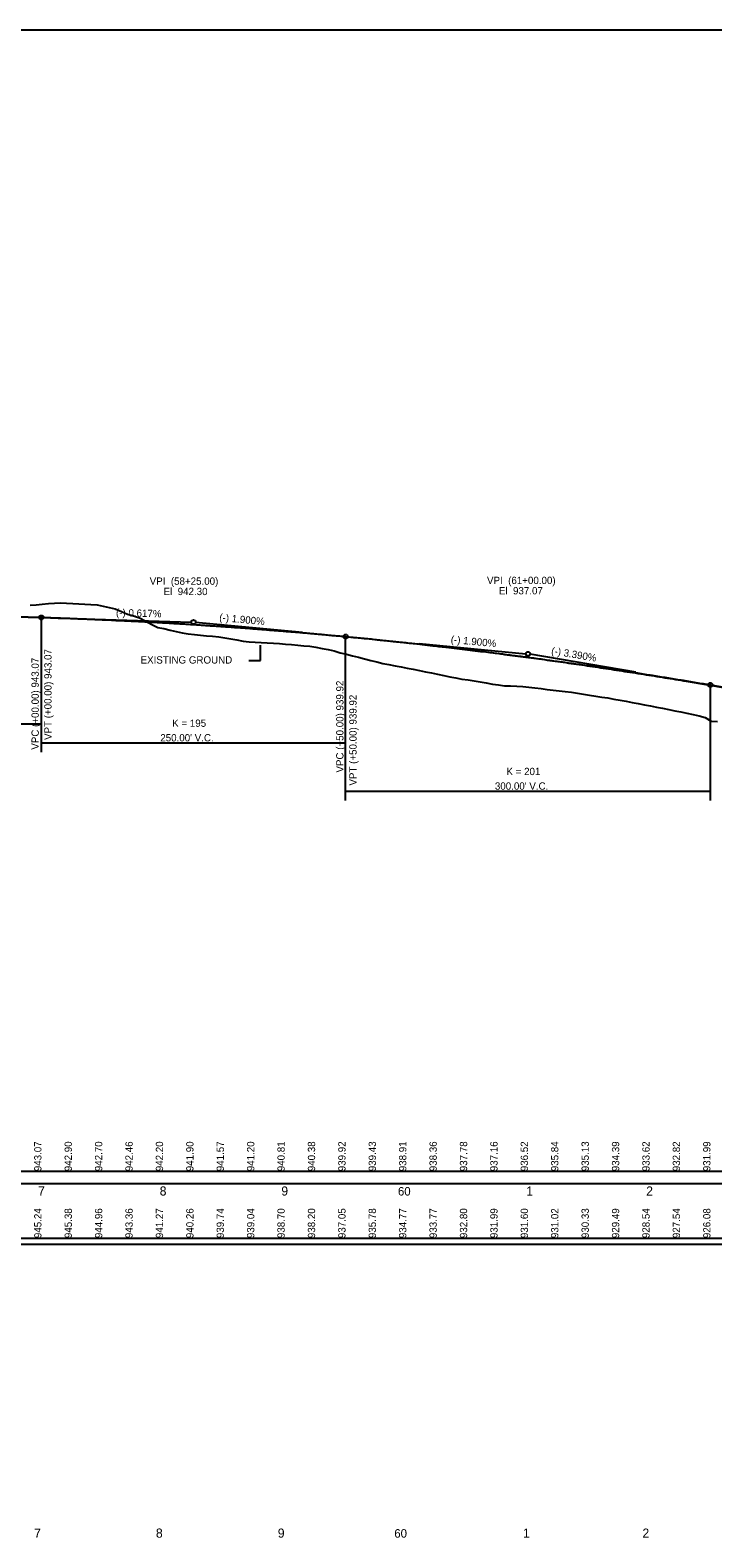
# Model space of a CAD drawing. Extents: x 16972094 to 16980746, y 12563782 to 12565536.
# Drawn here: x 16973711 to 16974272, y 12563996 to 12565236 of the extents above; entities that cross this region are included whole.
import ezdxf

# ---------------------------------------------------------------- set-up
doc = ezdxf.new("R2010")
doc.units = 0
for name, color, linetype in [('Default', 7, 'Continuous'), ('RD_DDB_EX_Tx', 7, 'Continuous'), ('RD_DTM_BkLn1', 7, 'Continuous'), ('RD_EX_BldgChurch', 7, 'Continuous'), ('RD_EX_Fence_ChLk', 7, 'Continuous'), ('RD_EX_H2O', 7, 'Continuous'), ('RD_EX_H2O_Ditch Bottom', 7, 'Continuous'), ('RD_PD_Supershp_I385', 7, 'Continuous'), ('RD_PD_Supershp_Ramp_7', 7, 'Continuous'), ('RD_Sketch2', 7, 'Continuous'), ('RD_Sketch3', 7, 'Continuous'), ('RD_TX_RoadID', 7, 'Continuous'), ('S_HydraCrossSection', 7, 'Continuous')]:
    doc.layers.add(name, color=color, linetype=linetype)

msp = doc.modelspace()

# ---------------------------------------------------------------- linework, layer by layer
at = {"layer": 'Default'}
msp.add_lwpolyline([(16972919.9, 12564237.8), (16974419.9, 12564237.8), (16974419.9, 12565236), (16972919.9, 12565236)], close=True, dxfattribs=at)
at = {"layer": 'RD_DDB_EX_Tx'}
for p, q in [((16973900, 12564717.7), (16973900, 12564730.3)), ((16973890.3, 12564717.7), (16973900, 12564717.7))]:
    msp.add_line(p, q, dxfattribs=at)
at = {"layer": 'RD_DTM_BkLn1'}
for p, q in [((16972919.9, 12564297.8), (16974419.9, 12564297.8)), ((16972919.9, 12564242.8), (16974419.9, 12564242.8))]:
    msp.add_line(p, q, dxfattribs=at)
at = {"layer": 'RD_EX_BldgChurch'}
for points in [[(16973710.6, 12564763.1), (16973715.6, 12564763.5), (16973720.6, 12564764.1), (16973725.6, 12564764.6), (16973730.6, 12564764.8), (16973735.6, 12564765.1), (16973740.6, 12564765), (16973745.6, 12564764.7), (16973750.6, 12564764.3), (16973755.6, 12564764), (16973760.6, 12564763.7), (16973765.6, 12564763.4), (16973770.6, 12564762.4), (16973775.6, 12564761.4), (16973780.6, 12564760.3), (16973785.6, 12564758.1), (16973790.6, 12564755.7), (16973795.6, 12564754.4), (16973800.6, 12564752.7), (16973805.6, 12564750.1), (16973810.6, 12564747.4), (16973815.6, 12564744.8), (16973820.6, 12564744), (16973825.6, 12564742.8), (16973830.6, 12564741.6), (16973835.6, 12564740.6), (16973840.6, 12564739.6), (16973845.6, 12564739), (16973850.6, 12564738.6), (16973855.6, 12564738.1), (16973860.6, 12564737.6), (16973865.6, 12564737.2), (16973870.6, 12564736.4), (16973875.6, 12564735.5), (16973880.6, 12564734.6), (16973885.6, 12564733.7), (16973890.6, 12564733.2), (16973895.6, 12564732.9), (16973900.6, 12564732.6), (16973905.6, 12564732.3), (16973910.6, 12564732), (16973915.6, 12564731.7), (16973920.6, 12564731.2), (16973925.6, 12564730.8), (16973930.6, 12564730.3), (16973935.6, 12564729.8), (16973940.6, 12564729.4), (16973945.6, 12564728.7), (16973950.6, 12564727.7), (16973955.6, 12564726.7), (16973960.6, 12564725.7), (16973965.6, 12564724.1), (16973970.6, 12564722.9), (16973975.6, 12564721.6), (16973980.6, 12564720.4), (16973985.6, 12564719.1)], [(16973985.6, 12564719.1), (16973990.6, 12564717.8), (16973995.6, 12564716.5), (16974000.6, 12564715.3), (16974005.6, 12564714.4), (16974010.6, 12564713.4), (16974015.6, 12564712.5), (16974020.6, 12564711.5), (16974025.6, 12564710.5), (16974030.6, 12564709.5), (16974035.6, 12564708.5), (16974040.6, 12564707.5), (16974045.6, 12564706.5), (16974050.6, 12564705.5), (16974055.6, 12564704.4), (16974060.6, 12564703.4), (16974065.6, 12564702.5), (16974070.6, 12564701.7), (16974075.6, 12564700.9), (16974080.6, 12564700.1), (16974085.6, 12564699.3), (16974090.6, 12564698.4), (16974095.6, 12564697.6), (16974100.6, 12564697), (16974105.6, 12564697), (16974110.6, 12564696.7), (16974115.6, 12564696.3), (16974120.6, 12564695.7), (16974125.6, 12564695.2), (16974130.6, 12564694.6), (16974135.6, 12564694), (16974140.6, 12564693.4), (16974145.6, 12564692.8), (16974150.6, 12564692.2), (16974155.6, 12564691.6), (16974160.6, 12564690.9), (16974165.6, 12564690.1), (16974170.6, 12564689.3), (16974175.6, 12564688.5), (16974180.6, 12564687.7), (16974185.6, 12564686.9), (16974190.6, 12564686), (16974195.6, 12564685.1), (16974200.6, 12564684.2), (16974205.6, 12564683.3), (16974210.6, 12564682.3), (16974215.6, 12564681.3), (16974220.6, 12564680.4), (16974225.6, 12564679.4), (16974230.6, 12564678.4), (16974235.6, 12564677.4), (16974240.6, 12564676.4), (16974245.6, 12564675.4), (16974250.6, 12564674.3), (16974255.6, 12564673.2), (16974260.6, 12564672.1), (16974265.6, 12564670.9), (16974270.6, 12564667.8), (16974275.6, 12564667.5)]]:
    msp.add_lwpolyline(points, dxfattribs=at)
at = {"layer": 'RD_EX_Fence_ChLk'}
msp.add_line((16972985.6, 12564287.8), (16980051.3, 12564287.8), dxfattribs=at)
at = {"layer": 'RD_EX_H2O_Ditch Bottom'}
for p, q in [((16973754.9, 12564752.1), (16973843.1, 12564749.3)), ((16973934.5, 12564740.8), (16973846.6, 12564749.1)), ((16974030.3, 12564731.7), (16974118.1, 12564723.3)), ((16974208.6, 12564708.1), (16974121.6, 12564722.9))]:
    msp.add_line(p, q, dxfattribs=at)
for centre in [(16973844.9, 12564749.3), (16974119.9, 12564723.2)]:
    msp.add_circle(centre, 1.75, dxfattribs=at)
at = {"layer": 'RD_Sketch2'}
for p, q in [((16973719.9, 12564658.1), (16973719.9, 12564751.4)), ((16973719.9, 12564642.4), (16973719.9, 12564751.4)), ((16973969.9, 12564642.4), (16973969.9, 12564735.7)), ((16973969.9, 12564602.7), (16973969.9, 12564735.7)), ((16974269.9, 12564602.7), (16974269.9, 12564696)), ((16973519.9, 12564665.6), (16973719.9, 12564665.6)), ((16973719.9, 12564649.9), (16973969.9, 12564649.9)), ((16973969.9, 12564610.2), (16974269.9, 12564610.2))]:
    msp.add_line(p, q, dxfattribs=at)
for centre in [(16973719.9, 12564753.1), (16973719.9, 12564753.1), (16973969.9, 12564737.4), (16973969.9, 12564737.4), (16974269.9, 12564697.7)]:
    msp.add_circle(centre, 1.75, dxfattribs=at)
at = {"layer": 'RD_Sketch3'}
msp.add_line((16974249.9, 12564700.7), (16974449.9, 12564667.2), dxfattribs=at)
for points in [[(16973519.9, 12564754.3), (16973619.9, 12564756.2), (16973719.9, 12564753.2)], [(16973719.9, 12564753.2), (16973844.9, 12564749.3), (16973969.9, 12564737.4)], [(16973969.9, 12564737.4), (16974109.9, 12564724.1), (16974249.9, 12564700.7)]]:
    msp.add_open_spline(points, degree=2, dxfattribs=at)
at = {"layer": 'RD_TX_RoadID'}
msp.add_line((16974269.9, 12564697.7), (16974419.9, 12564672.3), dxfattribs=at)
for points in [[(16973519.9, 12564754.3), (16973523.9, 12564754.4), (16973527.9, 12564754.5), (16973531.9, 12564754.5), (16973535.9, 12564754.6), (16973539.9, 12564754.7), (16973543.9, 12564754.7), (16973547.9, 12564754.8), (16973551.9, 12564754.8), (16973555.9, 12564754.9), (16973559.9, 12564754.9), (16973563.9, 12564754.9), (16973567.9, 12564755), (16973571.9, 12564755), (16973575.9, 12564755), (16973579.9, 12564755), (16973583.9, 12564755), (16973587.9, 12564755), (16973591.9, 12564755), (16973595.9, 12564755.1), (16973599.9, 12564755), (16973603.9, 12564755), (16973607.9, 12564755), (16973611.9, 12564755), (16973615.9, 12564755), (16973619.9, 12564755), (16973623.9, 12564755), (16973627.9, 12564754.9), (16973631.9, 12564754.9), (16973635.9, 12564754.9), (16973639.9, 12564754.8), (16973643.9, 12564754.8), (16973647.9, 12564754.7), (16973651.9, 12564754.7), (16973655.9, 12564754.6), (16973659.9, 12564754.5), (16973663.9, 12564754.5), (16973667.9, 12564754.4), (16973671.9, 12564754.3), (16973675.9, 12564754.3), (16973679.9, 12564754.2), (16973683.9, 12564754.1), (16973687.9, 12564754), (16973691.9, 12564753.9), (16973695.9, 12564753.8), (16973699.9, 12564753.7), (16973703.9, 12564753.6), (16973707.9, 12564753.5), (16973711.9, 12564753.4), (16973715.9, 12564753.3), (16973719.9, 12564753.1)], [(16973719.9, 12564753.1), (16973724.9, 12564753), (16973729.9, 12564752.8), (16973734.9, 12564752.6), (16973739.9, 12564752.5), (16973744.9, 12564752.3), (16973749.9, 12564752.1), (16973754.9, 12564751.9), (16973759.9, 12564751.7), (16973764.9, 12564751.5), (16973769.9, 12564751.3), (16973774.9, 12564751.1), (16973779.9, 12564750.8), (16973784.9, 12564750.6), (16973789.9, 12564750.4), (16973794.9, 12564750.1), (16973799.9, 12564749.9), (16973804.9, 12564749.6), (16973809.9, 12564749.3), (16973814.9, 12564749.1), (16973819.9, 12564748.8), (16973824.9, 12564748.5), (16973829.9, 12564748.2), (16973834.9, 12564747.9), (16973839.9, 12564747.6), (16973844.9, 12564747.3), (16973849.9, 12564747), (16973854.9, 12564746.6), (16973859.9, 12564746.3), (16973864.9, 12564746), (16973869.9, 12564745.6), (16973874.9, 12564745.3), (16973879.9, 12564744.9), (16973884.9, 12564744.6), (16973889.9, 12564744.2), (16973894.9, 12564743.8), (16973899.9, 12564743.4), (16973904.9, 12564743), (16973909.9, 12564742.6), (16973914.9, 12564742.2), (16973919.9, 12564741.8), (16973924.9, 12564741.4), (16973929.9, 12564741), (16973934.9, 12564740.6), (16973939.9, 12564740.1), (16973944.9, 12564739.7), (16973949.9, 12564739.3), (16973954.9, 12564738.8), (16973959.9, 12564738.3), (16973964.9, 12564737.9), (16973969.9, 12564737.4)], [(16973969.9, 12564737.4), (16973975.9, 12564736.8), (16973981.9, 12564736.3), (16973987.9, 12564735.7), (16973993.9, 12564735.1), (16973999.9, 12564734.4), (16974005.9, 12564733.8), (16974011.9, 12564733.2), (16974017.9, 12564732.6), (16974023.9, 12564731.9), (16974029.9, 12564731.3), (16974035.9, 12564730.6), (16974041.9, 12564729.9), (16974047.9, 12564729.2), (16974053.9, 12564728.6), (16974059.9, 12564727.9), (16974065.9, 12564727.1), (16974071.9, 12564726.4), (16974077.9, 12564725.7), (16974083.9, 12564725), (16974089.9, 12564724.2), (16974095.9, 12564723.5), (16974101.9, 12564722.7), (16974107.9, 12564721.9), (16974113.9, 12564721.2), (16974119.9, 12564720.4), (16974125.9, 12564719.6), (16974131.9, 12564718.8), (16974137.9, 12564717.9), (16974143.9, 12564717.1), (16974149.9, 12564716.3), (16974155.9, 12564715.4), (16974161.9, 12564714.6), (16974167.9, 12564713.7), (16974173.9, 12564712.9), (16974179.9, 12564712), (16974185.9, 12564711.1), (16974191.9, 12564710.2), (16974197.9, 12564709.3), (16974203.9, 12564708.4), (16974209.9, 12564707.5), (16974215.9, 12564706.5), (16974221.9, 12564705.6), (16974227.9, 12564704.6), (16974233.9, 12564703.7), (16974239.9, 12564702.7), (16974245.9, 12564701.7), (16974251.9, 12564700.7), (16974257.9, 12564699.7), (16974263.9, 12564698.7), (16974269.9, 12564697.7)]]:
    msp.add_spline(points, degree=3, dxfattribs=at)

# ---------------------------------------------------------------- texts
at = {"layer": 'RD_DDB_EX_Tx'}
msp.add_text('EXISTING GROUND', height=6, dxfattribs=at).set_placement((16973801.4, 12564715.2))
at = {"layer": 'RD_EX_H2O'}
for s, height, p in [('7', 7.5, (16973717.1, 12564277.8)), ('8', 7.5, (16973817.1, 12564277.8)), ('9', 7.5, (16973917.1, 12564277.8)), ('60', 7, (16974013, 12564277.8)), ('1', 7.5, (16974118.5, 12564277.8)), ('2', 7.5, (16974217.1, 12564277.8)), ('7', 7.5, (16973713.9, 12563996.5)), ('8', 7.5, (16973814, 12563996.5)), ('9', 7.5, (16973914.2, 12563996.5)), ('60', 7, (16974010, 12563996.5)), ('1', 7.5, (16974115.8, 12563996.5)), ('2', 7.5, (16974214, 12563996.5))]:
    msp.add_text(s, height=height, dxfattribs=at).set_placement(p)
at = {"layer": 'RD_EX_H2O_Ditch Bottom'}
for s, p in [('VPI  (58+25.00)', (16973808.9, 12564780)), ('VPI  (61+00.00)', (16974086.2, 12564780.6)), ('El  942.30', (16973820.3, 12564771.5)), ('El  937.07', (16974096, 12564772.1))]:
    msp.add_text(s, height=6, dxfattribs=at).set_placement(p)
at = {"layer": 'RD_PD_Supershp_I385'}
for s, p in [('943.07', (16973719.9, 12564297.8)), ('942.90', (16973744.9, 12564297.8)), ('942.70', (16973769.9, 12564297.8)), ('942.46', (16973794.9, 12564297.8)), ('942.20', (16973819.9, 12564297.8)), ('941.90', (16973844.9, 12564297.8)), ('941.57', (16973869.9, 12564297.8)), ('941.20', (16973894.9, 12564297.8)), ('940.81', (16973919.9, 12564297.8)), ('940.38', (16973944.9, 12564297.8)), ('939.92', (16973969.9, 12564297.8)), ('939.43', (16973994.9, 12564297.8)), ('938.91', (16974019.9, 12564297.8)), ('938.36', (16974044.9, 12564297.8)), ('937.78', (16974069.9, 12564297.8)), ('937.16', (16974094.9, 12564297.8)), ('936.52', (16974119.9, 12564297.8)), ('935.84', (16974144.9, 12564297.8)), ('935.13', (16974169.9, 12564297.8)), ('934.39', (16974194.9, 12564297.8)), ('933.62', (16974219.9, 12564297.8)), ('932.82', (16974244.9, 12564297.8)), ('931.99', (16974269.9, 12564297.8))]:
    msp.add_text(s, height=6, rotation=90, dxfattribs=at).set_placement(p)
at = {"layer": 'RD_PD_Supershp_Ramp_7'}
for s, p in [('945.24', (16973719.9, 12564242.8)), ('945.38', (16973744.9, 12564242.8)), ('944.96', (16973769.9, 12564242.8)), ('943.36', (16973794.9, 12564242.8)), ('941.27', (16973819.9, 12564242.8)), ('940.26', (16973844.9, 12564242.8)), ('939.74', (16973869.9, 12564242.8)), ('939.04', (16973894.9, 12564242.8)), ('938.70', (16973919.9, 12564242.8)), ('938.20', (16973944.9, 12564242.8)), ('937.05', (16973969.9, 12564242.8)), ('935.78', (16973994.9, 12564242.8)), ('934.77', (16974019.9, 12564242.8)), ('933.77', (16974044.9, 12564242.8)), ('932.80', (16974069.9, 12564242.8)), ('931.99', (16974094.9, 12564242.8)), ('931.60', (16974119.9, 12564242.8)), ('931.02', (16974144.9, 12564242.8)), ('930.33', (16974169.9, 12564242.8)), ('929.49', (16974194.9, 12564242.8)), ('928.54', (16974219.9, 12564242.8)), ('927.54', (16974244.9, 12564242.8)), ('926.08', (16974269.9, 12564242.8))]:
    msp.add_text(s, height=6, rotation=90, dxfattribs=at).set_placement(p)
at = {"layer": 'RD_Sketch2'}
for s, p in [('VPT (+00.00) 943.07', (16973728.2, 12564652.4)), ('VPC (+00.00) 943.07', (16973717.7, 12564644.4)), ('VPC (+50.00) 939.92', (16973968.2, 12564625.6)), ('VPT (+50.00) 939.92', (16973979, 12564614.9))]:
    msp.add_text(s, height=6, rotation=90, dxfattribs=at).set_placement(p)
for s, p in [('K = 195', (16973827.4, 12564663.2)), ("250.00' V.C.", (16973817.6, 12564651.2)), ('K = 201', (16974102.2, 12564623.5)), ("300.00' V.C.", (16974092.7, 12564611.5))]:
    msp.add_text(s, height=6, dxfattribs=at).set_placement(p)
at = {"layer": 'S_HydraCrossSection'}
for s, rotation, p in [('(-) 0.617%', 358.233, (16973781.1, 12564754.3)), ('(-) 1.900%', 354.5732, (16973865.9, 12564750.3)), ('(-) 1.900%', 354.5732, (16974056.2, 12564732.2)), ('(-) 3.390%', 350.3798, (16974138.7, 12564723))]:
    msp.add_text(s, height=6, rotation=rotation, dxfattribs=at).set_placement(p)

doc.saveas('drawing.dxf')
